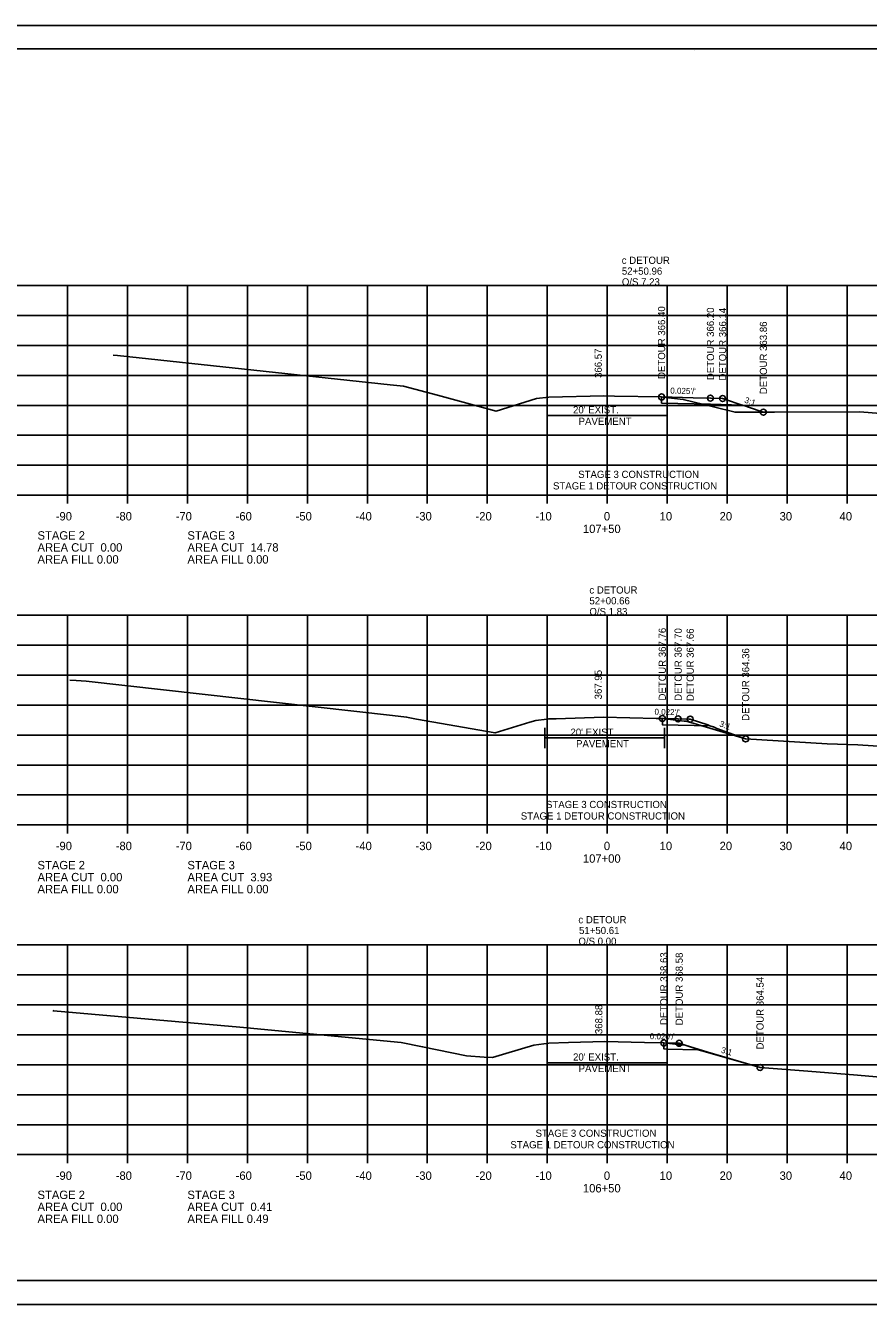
# Model space of a CAD drawing. Extents: x 1630712 to 1632516, y 782146 to 785403.
# Drawn here: x 1632236 to 1632376.5, y 783483.3 to 783696.6 of the extents above; entities that cross this region are included whole.
import ezdxf

# ---------------------------------------------------------------- set-up
doc = ezdxf.new("R2010")
doc.units = 0
for name, color, linetype in [('Notes', 7, 'Continuous'), ('R_Axis', 7, 'Continuous'), ('R_Axis Annot', 7, 'Continuous'), ('R_Border', 7, 'Continuous'), ('R_Detour Subgrade', 7, 'Continuous'), ('R_Detour Surface', 7, 'Continuous'), ('R_Exist Surface', 7, 'Continuous'), ('R_Grid', 7, 'Continuous'), ('R_No Plot', 7, 'Continuous'), ('R_Xsect Elev', 7, 'Continuous'), ('R_Xsect Elev Detour', 7, 'Continuous'), ('R_Xsect Slope', 7, 'Continuous')]:
    doc.layers.add(name, color=color, linetype=linetype)

msp = doc.modelspace()

# ---------------------------------------------------------------- linework, layer by layer
at = {"layer": 'Notes'}
for p, q in [((1632322.96, 783629.88), (1632322.96, 783633.28)), ((1632342.96, 783629.88), (1632342.96, 783633.28)), ((1632322.96, 783631.58), (1632342.96, 783631.58)), ((1632322.53, 783576.1), (1632322.53, 783579.5)), ((1632342.53, 783576.1), (1632342.53, 783579.5)), ((1632322.53, 783577.8), (1632342.53, 783577.8)), ((1632322.96, 783521.91), (1632322.96, 783525.31)), ((1632342.96, 783521.91), (1632342.96, 783525.31)), ((1632322.96, 783523.61), (1632342.96, 783523.61))]:
    msp.add_line(p, q, dxfattribs=at)
at = {"layer": 'R_Axis'}
for p, q in [((1632212.96, 783618.28), (1632492.96, 783618.28)), ((1632242.96, 783616.88), (1632242.96, 783618.28)), ((1632252.96, 783616.88), (1632252.96, 783618.28)), ((1632262.96, 783616.88), (1632262.96, 783618.28)), ((1632272.96, 783616.88), (1632272.96, 783618.28)), ((1632282.96, 783616.88), (1632282.96, 783618.28)), ((1632292.96, 783616.88), (1632292.96, 783618.28)), ((1632302.96, 783616.88), (1632302.96, 783618.28)), ((1632312.96, 783616.88), (1632312.96, 783618.28)), ((1632322.96, 783616.88), (1632322.96, 783618.28)), ((1632332.96, 783616.88), (1632332.96, 783618.28)), ((1632342.96, 783616.88), (1632342.96, 783618.28)), ((1632352.96, 783616.88), (1632352.96, 783618.28)), ((1632362.96, 783616.88), (1632362.96, 783618.28)), ((1632372.96, 783616.88), (1632372.96, 783618.28)), ((1632212.96, 783563.28), (1632492.96, 783563.28)), ((1632242.96, 783561.88), (1632242.96, 783563.28)), ((1632252.96, 783561.88), (1632252.96, 783563.28)), ((1632262.96, 783561.88), (1632262.96, 783563.28)), ((1632272.96, 783561.88), (1632272.96, 783563.28)), ((1632282.96, 783561.88), (1632282.96, 783563.28)), ((1632292.96, 783561.88), (1632292.96, 783563.28)), ((1632302.96, 783561.88), (1632302.96, 783563.28)), ((1632312.96, 783561.88), (1632312.96, 783563.28)), ((1632322.96, 783561.88), (1632322.96, 783563.28)), ((1632332.96, 783561.88), (1632332.96, 783563.28)), ((1632342.96, 783561.88), (1632342.96, 783563.28)), ((1632352.96, 783561.88), (1632352.96, 783563.28)), ((1632362.96, 783561.88), (1632362.96, 783563.28)), ((1632372.96, 783561.88), (1632372.96, 783563.28)), ((1632212.96, 783508.28), (1632492.96, 783508.28)), ((1632242.96, 783506.88), (1632242.96, 783508.28)), ((1632252.96, 783506.88), (1632252.96, 783508.28)), ((1632262.96, 783506.88), (1632262.96, 783508.28)), ((1632272.96, 783506.88), (1632272.96, 783508.28)), ((1632282.96, 783506.88), (1632282.96, 783508.28)), ((1632292.96, 783506.88), (1632292.96, 783508.28)), ((1632302.96, 783506.88), (1632302.96, 783508.28)), ((1632312.96, 783506.88), (1632312.96, 783508.28)), ((1632322.96, 783506.88), (1632322.96, 783508.28)), ((1632332.96, 783506.88), (1632332.96, 783508.28)), ((1632342.96, 783506.88), (1632342.96, 783508.28)), ((1632352.96, 783506.88), (1632352.96, 783508.28)), ((1632362.96, 783506.88), (1632362.96, 783508.28)), ((1632372.96, 783506.88), (1632372.96, 783508.28))]:
    msp.add_line(p, q, dxfattribs=at)
at = {"layer": 'R_Border'}
for p, q in [((1632194.96, 783692.74), (1632511.14, 783692.74)), ((1632347.48, 783692.48), (1632347.48, 783692.48)), ((1632347.48, 783692.48), (1632347.48, 783692.48)), ((1632511.14, 783487.28), (1632194.96, 783487.28))]:
    msp.add_line(p, q, dxfattribs=at)
at = {"layer": 'R_Detour Subgrade'}
for points in [[(1632342.02, 783634.68), (1632342.03, 783633.66), (1632350.17, 783633.46), (1632355.45, 783633.33)], [(1632342.02, 783634.68), (1632342.03, 783633.66), (1632350.17, 783633.46), (1632355.45, 783633.33)], [(1632342.14, 783581.04), (1632342.15, 783580.01), (1632344.78, 783579.95), (1632350.09, 783579.84)], [(1632342.14, 783581.04), (1632342.15, 783580.01), (1632344.78, 783579.95), (1632350.09, 783579.84)], [(1632342.4, 783526.91), (1632342.41, 783525.91), (1632342.96, 783525.9), (1632348.15, 783525.79)], [(1632342.4, 783526.91), (1632342.41, 783525.91), (1632342.96, 783525.9), (1632348.15, 783525.79)]]:
    msp.add_lwpolyline(points, dxfattribs=at)
at = {"layer": 'R_Detour Surface'}
for points in [[(1632342.02, 783634.68), (1632347.27, 783634.55), (1632350.17, 783634.48), (1632350.28, 783634.47), (1632352.19, 783634.42), (1632352.49, 783634.33), (1632355.45, 783633.33), (1632355.54, 783633.3), (1632356.06, 783633.13), (1632356.53, 783632.97), (1632358.97, 783632.15)], [(1632342.14, 783581.04), (1632342.34, 783581.04), (1632344.78, 783580.98), (1632346.61, 783580.94), (1632346.79, 783580.94), (1632349.71, 783579.96), (1632350.09, 783579.84), (1632350.62, 783579.66), (1632350.69, 783579.64), (1632351.26, 783579.4), (1632356.04, 783577.64)], [(1632342.4, 783526.91), (1632342.4, 783526.91), (1632342.96, 783526.9), (1632344.96, 783526.86), (1632344.96, 783526.86), (1632348.14, 783525.8), (1632348.15, 783525.79), (1632348.75, 783525.6), (1632348.75, 783525.59), (1632348.76, 783525.59), (1632358.44, 783522.82)]]:
    msp.add_lwpolyline(points, dxfattribs=at)
at = {"layer": 'R_Exist Surface'}
for points in [[(1632250.57, 783641.63), (1632251.3, 783641.59), (1632296.79, 783636.72), (1632298.99, 783636.48), (1632304.64, 783634.96), (1632314.45, 783632.3), (1632321.14, 783634.41), (1632321.16, 783634.42), (1632321.17, 783634.42), (1632323.2, 783634.62), (1632323.25, 783634.62), (1632332.39, 783634.86), (1632334.19, 783634.82), (1632342.02, 783634.68), (1632342.23, 783634.66), (1632345.65, 783634.25), (1632350.67, 783633.02), (1632354.27, 783632.13), (1632360.85, 783632.16), (1632375.08, 783632.19), (1632388.88, 783631.07)], [(1632243.36, 783587.42), (1632244.41, 783587.36), (1632246.08, 783587.26), (1632297.13, 783581.54), (1632299.5, 783581.28), (1632301.17, 783580.95), (1632314.26, 783578.64), (1632320.08, 783580.41), (1632321.06, 783580.72), (1632322.9, 783580.94), (1632323.18, 783580.97), (1632324.43, 783581), (1632332.36, 783581.25), (1632341.11, 783581.06), (1632342.14, 783581.04), (1632345.8, 783580.62), (1632346.09, 783580.59), (1632346.88, 783580.36), (1632356.04, 783577.64), (1632369.62, 783576.83), (1632374.73, 783576.63), (1632385.82, 783575.91)], [(1632240.54, 783532.35), (1632240.63, 783532.3), (1632271.71, 783529.54), (1632298.62, 783526.99), (1632302.16, 783526.29), (1632309.52, 783524.75), (1632312.46, 783524.56), (1632313.81, 783524.47), (1632316.05, 783525.14), (1632320.7, 783526.54), (1632321.54, 783526.65), (1632323.24, 783526.87), (1632326.52, 783526.98), (1632332.58, 783527.17), (1632339.18, 783526.99), (1632342.4, 783526.91), (1632344.78, 783526.65), (1632345.96, 783526.52), (1632349.71, 783525.39), (1632358.44, 783522.82), (1632366.43, 783522.2), (1632374.68, 783521.56), (1632392.43, 783519.99)]]:
    msp.add_lwpolyline(points, dxfattribs=at)
at = {"layer": 'R_Grid'}
for p, q in [((1632212.96, 783653.28), (1632492.96, 783653.28)), ((1632242.96, 783618.28), (1632242.96, 783653.28)), ((1632252.96, 783618.28), (1632252.96, 783653.28)), ((1632262.96, 783618.28), (1632262.96, 783653.28)), ((1632272.96, 783618.28), (1632272.96, 783653.28)), ((1632282.96, 783618.28), (1632282.96, 783653.28)), ((1632292.96, 783618.28), (1632292.96, 783653.28)), ((1632302.96, 783618.28), (1632302.96, 783653.28)), ((1632312.96, 783618.28), (1632312.96, 783653.28)), ((1632322.96, 783618.28), (1632322.96, 783653.28)), ((1632332.96, 783618.28), (1632332.96, 783653.28)), ((1632342.96, 783618.28), (1632342.96, 783653.28)), ((1632352.96, 783618.28), (1632352.96, 783653.28)), ((1632362.96, 783618.28), (1632362.96, 783653.28)), ((1632372.96, 783618.28), (1632372.96, 783653.28)), ((1632212.96, 783648.28), (1632492.96, 783648.28)), ((1632212.96, 783643.28), (1632492.96, 783643.28)), ((1632212.96, 783638.28), (1632492.96, 783638.28)), ((1632212.96, 783633.28), (1632492.96, 783633.28)), ((1632212.96, 783628.28), (1632492.96, 783628.28)), ((1632212.96, 783623.28), (1632492.96, 783623.28)), ((1632212.96, 783618.28), (1632492.96, 783618.28)), ((1632212.96, 783598.28), (1632492.96, 783598.28)), ((1632242.96, 783563.28), (1632242.96, 783598.28)), ((1632252.96, 783563.28), (1632252.96, 783598.28)), ((1632262.96, 783563.28), (1632262.96, 783598.28)), ((1632272.96, 783563.28), (1632272.96, 783598.28)), ((1632282.96, 783563.28), (1632282.96, 783598.28)), ((1632292.96, 783563.28), (1632292.96, 783598.28)), ((1632302.96, 783563.28), (1632302.96, 783598.28)), ((1632312.96, 783563.28), (1632312.96, 783598.28)), ((1632322.96, 783563.28), (1632322.96, 783598.28)), ((1632332.96, 783563.28), (1632332.96, 783598.28)), ((1632342.96, 783563.28), (1632342.96, 783598.28)), ((1632352.96, 783563.28), (1632352.96, 783598.28)), ((1632362.96, 783563.28), (1632362.96, 783598.28)), ((1632372.96, 783563.28), (1632372.96, 783598.28)), ((1632212.96, 783593.28), (1632492.96, 783593.28)), ((1632212.96, 783588.28), (1632492.96, 783588.28)), ((1632212.96, 783583.28), (1632492.96, 783583.28)), ((1632212.96, 783578.28), (1632492.96, 783578.28)), ((1632212.96, 783573.28), (1632492.96, 783573.28)), ((1632212.96, 783568.28), (1632492.96, 783568.28)), ((1632212.96, 783563.28), (1632492.96, 783563.28)), ((1632212.96, 783543.28), (1632492.96, 783543.28)), ((1632242.96, 783508.28), (1632242.96, 783543.28)), ((1632252.96, 783508.28), (1632252.96, 783543.28)), ((1632262.96, 783508.28), (1632262.96, 783543.28)), ((1632272.96, 783508.28), (1632272.96, 783543.28)), ((1632282.96, 783508.28), (1632282.96, 783543.28)), ((1632292.96, 783508.28), (1632292.96, 783543.28)), ((1632302.96, 783508.28), (1632302.96, 783543.28)), ((1632312.96, 783508.28), (1632312.96, 783543.28)), ((1632322.96, 783508.28), (1632322.96, 783543.28)), ((1632332.96, 783508.28), (1632332.96, 783543.28)), ((1632342.96, 783508.28), (1632342.96, 783543.28)), ((1632352.96, 783508.28), (1632352.96, 783543.28)), ((1632362.96, 783508.28), (1632362.96, 783543.28)), ((1632372.96, 783508.28), (1632372.96, 783543.28)), ((1632212.96, 783538.28), (1632492.96, 783538.28)), ((1632212.96, 783533.28), (1632492.96, 783533.28)), ((1632212.96, 783528.28), (1632492.96, 783528.28)), ((1632212.96, 783523.28), (1632492.96, 783523.28)), ((1632212.96, 783518.28), (1632492.96, 783518.28)), ((1632212.96, 783513.28), (1632492.96, 783513.28)), ((1632212.96, 783508.28), (1632492.96, 783508.28))]:
    msp.add_line(p, q, dxfattribs=at)
at = {"layer": 'R_No Plot'}
for p, q in [((1632182.56, 783696.63), (1632515.9, 783696.63)), ((1632182.56, 783483.3), (1632515.9, 783483.3))]:
    msp.add_line(p, q, dxfattribs=at)
msp.add_lwpolyline([(1632182.56, 783696.63), (1632515.9, 783696.63), (1632515.9, 783483.3), (1632182.56, 783483.3)], close=True, dxfattribs=at)
for centre in [(1632342.02, 783634.68), (1632350.17, 783634.48), (1632352.19, 783634.42), (1632359, 783632.14), (1632342.14, 783581.04), (1632344.78, 783580.98), (1632346.79, 783580.94), (1632356.04, 783577.64), (1632356.04, 783577.64), (1632342.4, 783526.91), (1632344.96, 783526.86), (1632358.44, 783522.82), (1632358.44, 783522.82)]:
    msp.add_circle(centre, 0.5, dxfattribs=at)

# ---------------------------------------------------------------- texts
at = {"layer": 'Notes'}
for s, p in [('c DETOUR', (1632335.38, 783656.88)), ('52+50.96', (1632335.4, 783655.08)), ('O/S 7.23', (1632335.4, 783653.28)), ("20' EXIST.", (1632327.26, 783631.94)), ('PAVEMENT', (1632328.19, 783630.02)), ('STAGE 3 CONSTRUCTION', (1632328.12, 783621.17)), ('STAGE 1 DETOUR CONSTRUCTION', (1632323.92, 783619.25)), ('c DETOUR', (1632329.98, 783601.88)), ('52+00.66', (1632329.99, 783600.08)), ('O/S 1.83', (1632329.99, 783598.28)), ("20' EXIST.", (1632326.83, 783578.16)), ('PAVEMENT', (1632327.76, 783576.24)), ('STAGE 3 CONSTRUCTION', (1632322.75, 783566.1)), ('STAGE 1 DETOUR CONSTRUCTION', (1632318.55, 783564.18)), ('c DETOUR', (1632328.15, 783546.88)), ('O/S 0.00', (1632328.16, 783543.28)), ('51+50.61', (1632328.26, 783545.08)), ("20' EXIST.", (1632327.26, 783523.97)), ('PAVEMENT', (1632328.19, 783522.05)), ('STAGE 3 CONSTRUCTION', (1632321.01, 783511.26)), ('STAGE 1 DETOUR CONSTRUCTION', (1632316.81, 783509.34))]:
    msp.add_text(s, height=1.2, dxfattribs=at).set_placement(p)
at = {"layer": 'R_Axis Annot'}
for s, p in [('-90', (1632241, 783614.08)), ('-80', (1632251, 783614.08)), ('-70', (1632261, 783614.08)), ('-60', (1632271, 783614.08)), ('-50', (1632281, 783614.08)), ('-40', (1632291, 783614.08)), ('-30', (1632301, 783614.08)), ('-20', (1632311, 783614.08)), ('-10', (1632321, 783614.08)), ('0', (1632332.4, 783614.08)), ('10', (1632341.7, 783614.08)), ('20', (1632351.7, 783614.08)), ('30', (1632361.7, 783614.08)), ('40', (1632371.7, 783614.08)), ('107+50', (1632328.9, 783611.98)), ('STAGE 2', (1632237.96, 783610.88)), ('STAGE 3', (1632262.96, 783610.88)), ('AREA CUT  0.00', (1632237.96, 783608.88)), ('AREA FILL 0.00', (1632237.96, 783606.88)), ('AREA CUT  14.78', (1632262.96, 783608.88)), ('AREA FILL 0.00', (1632262.96, 783606.88)), ('-90', (1632241, 783559.08)), ('-80', (1632251, 783559.08)), ('-70', (1632261, 783559.08)), ('-60', (1632271, 783559.08)), ('-50', (1632281, 783559.08)), ('-40', (1632291, 783559.08)), ('-30', (1632301, 783559.08)), ('-20', (1632311, 783559.08)), ('-10', (1632321, 783559.08)), ('0', (1632332.4, 783559.08)), ('10', (1632341.7, 783559.08)), ('20', (1632351.7, 783559.08)), ('30', (1632361.7, 783559.08)), ('40', (1632371.7, 783559.08)), ('STAGE 2', (1632237.96, 783555.88)), ('STAGE 3', (1632262.96, 783555.88)), ('107+00', (1632328.9, 783556.98)), ('AREA CUT  0.00', (1632237.96, 783553.88)), ('AREA CUT  3.93', (1632262.96, 783553.88)), ('AREA FILL 0.00', (1632237.96, 783551.88)), ('AREA FILL 0.00', (1632262.96, 783551.88)), ('-90', (1632241, 783504.08)), ('-80', (1632251, 783504.08)), ('-70', (1632261, 783504.08)), ('-60', (1632271, 783504.08)), ('-50', (1632281, 783504.08)), ('-40', (1632291, 783504.08)), ('-30', (1632301, 783504.08)), ('-20', (1632311, 783504.08)), ('-10', (1632321, 783504.08)), ('0', (1632332.4, 783504.08)), ('10', (1632341.7, 783504.08)), ('20', (1632351.7, 783504.08)), ('30', (1632361.7, 783504.08)), ('40', (1632371.7, 783504.08)), ('STAGE 2', (1632237.96, 783500.88)), ('STAGE 3', (1632262.96, 783500.88)), ('106+50', (1632328.9, 783501.98)), ('AREA CUT  0.00', (1632237.96, 783498.88)), ('AREA CUT  0.41', (1632262.96, 783498.88)), ('AREA FILL 0.00', (1632237.96, 783496.88)), ('AREA FILL 0.49', (1632262.96, 783496.88))]:
    msp.add_text(s, height=1.4, dxfattribs=at).set_placement(p)
at = {"layer": 'R_Xsect Elev'}
for s, p in [('366.57', (1632332.06, 783637.85)), ('367.95', (1632332.06, 783584.23)), ('368.88', (1632332.15, 783528.39))]:
    msp.add_text(s, height=1.2, rotation=90, dxfattribs=at).set_placement(p)
at = {"layer": 'R_Xsect Elev Detour'}
for s, p in [('DETOUR 366.40', (1632342.62, 783637.68)), ('DETOUR 366.20', (1632350.77, 783637.48)), ('DETOUR 366.14', (1632352.79, 783637.42)), ('DETOUR 363.86', (1632359.6, 783635.14)), ('DETOUR 367.76', (1632342.74, 783584.04)), ('DETOUR 367.70', (1632345.38, 783583.98)), ('DETOUR 367.66', (1632347.39, 783583.94)), ('DETOUR 364.36', (1632356.64, 783580.64)), ('DETOUR 368.63', (1632343, 783529.91)), ('DETOUR 368.58', (1632345.56, 783529.86)), ('DETOUR 364.54', (1632359.04, 783525.82))]:
    msp.add_text(s, height=1.2, rotation=90, dxfattribs=at).set_placement(p)
at = {"layer": 'R_Xsect Slope'}
for s, rotation, p in [("0.025'/'", 358.548, (1632343.47, 783635.25)), ('3:1', 341.4587, (1632355.76, 783633.76)), ("0.022'/'", 358.7497, (1632340.83, 783581.67)), ('3:1', 340.3685, (1632351.58, 783579.76)), ("0.020'/'", 358.8535, (1632340.05, 783527.55)), ('3:1', 343.3256, (1632351.85, 783525.32))]:
    msp.add_text(s, height=1, rotation=rotation, dxfattribs=at).set_placement(p)

doc.saveas('drawing.dxf')
